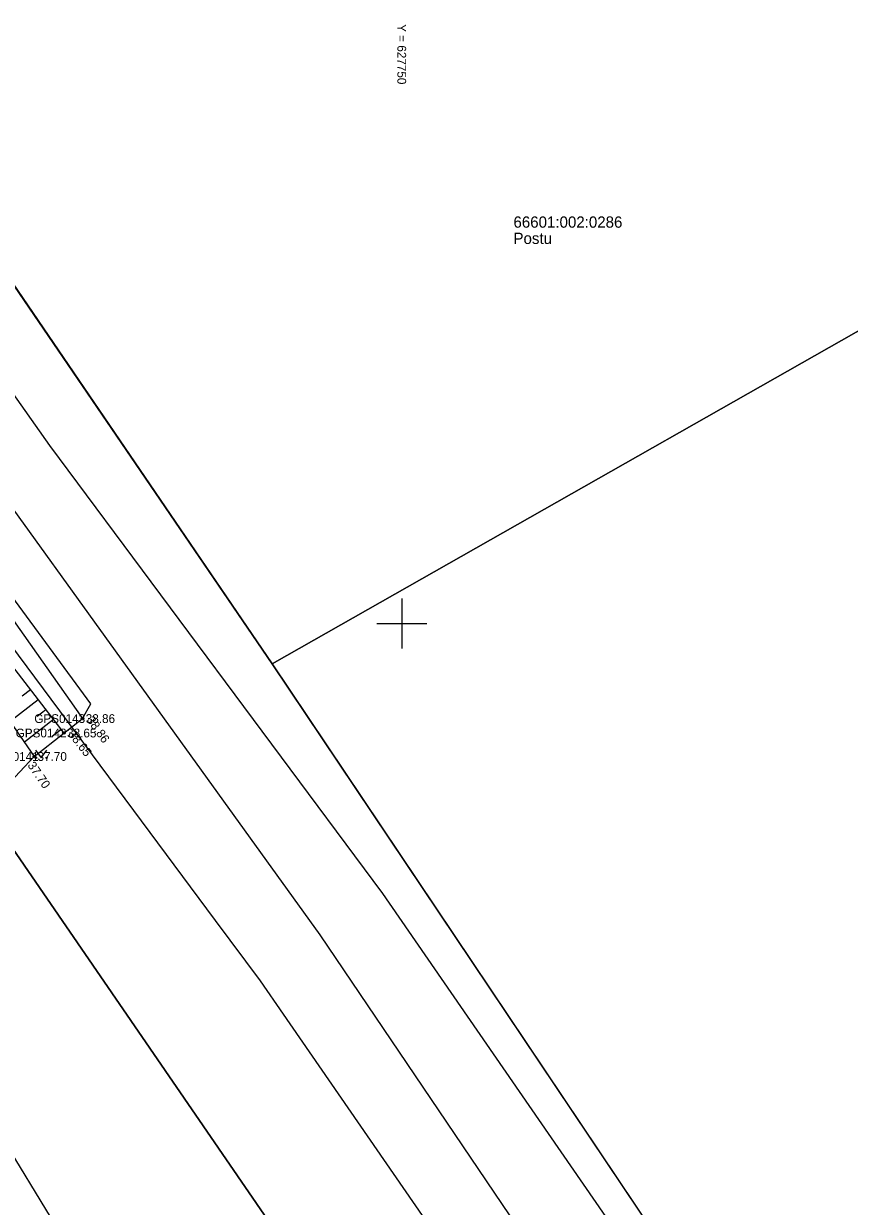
# Model space of a CAD drawing. Extents: x 626224 to 628280, y 6467750 to 6471135.
# Drawn here: x 627719.8 to 627785.8, y 6468553.4 to 6468647.9 of the extents above; entities that cross this region are included whole.
import ezdxf

# ---------------------------------------------------------------- set-up
doc = ezdxf.new("R2010")
doc.units = 0
for name, color, linetype in [('HALJASTUS', 7, 'Continuous'), ('KORGUS-EH2000', 7, 'Continuous'), ('MOOTKORG-EH2000', 7, 'Continuous'), ('MOOTMPUNKT', 7, 'Continuous'), ('MOOTNR', 7, 'Continuous'), ('MOOTPIIR', 7, 'Continuous'), ('MPOHULIIN', 7, 'Continuous'), ('PIIR', 7, 'Continuous'), ('RELJEEF', 7, 'Continuous'), ('TEE', 7, 'Continuous'), ('Tee Liiklusala', 7, 'Continuous'), ('Tee Põhimaantee Püsikate', 7, 'Continuous'), ('VORK', 7, 'Continuous')]:
    doc.layers.add(name, color=color, linetype=linetype)

msp = doc.modelspace()

# ---------------------------------------------------------------- linework, layer by layer
at = {"layer": 'HALJASTUS'}
for p, q in [((627720.731, 6468589.858), (627721.195, 6468589.252)), ((627721.195, 6468589.252), (627721.64, 6468589.858))]:
    msp.add_line(p, q, dxfattribs=at)
for centre in [(627720.794, 6468589.252), (627721.622, 6468589.252)]:
    msp.add_circle(centre, 0.055, dxfattribs=at)
at = {"layer": 'KORGUS-EH2000'}
for centre in [(627724.497, 6468592.392), (627723.007, 6468591.238), (627720.646, 6468589.364)]:
    msp.add_circle(centre, 0.1, dxfattribs=at)
at = {"layer": 'MOOTMPUNKT'}
for centre in [(627724.497, 6468592.392), (627723.007, 6468591.238), (627720.646, 6468589.364)]:
    msp.add_circle(centre, 0.1, dxfattribs=at)
at = {"layer": 'MOOTPIIR'}
msp.add_lwpolyline([(627717.166, 6468585.678), (627720.646, 6468589.364), (627723.007, 6468591.238), (627724.497, 6468592.392), (627725.17, 6468593.561), (627699.891, 6468628.007)], dxfattribs=at)
at = {"layer": 'MPOHULIIN'}
msp.add_lwpolyline([(627776.772, 6468462.547), (627753.896, 6468500.245), (627726.889, 6468544.419), (627704.355, 6468581.436)], dxfattribs=at)
at = {"layer": 'PIIR'}
for points in [[(627433.19, 6469529.94), (627459.99, 6469400.72), (627467.62, 6469361.51), (627515.86, 6469120.25), (627514.14, 6469119.89), (627516.34, 6469107.19), (627530.89, 6469025.52), (627552.51, 6468945.46), (627573.42, 6468886.37), (627594.9, 6468837.52), (627616.28, 6468794.59), (627647.89, 6468735.54), (627664.81, 6468708.59), (627667, 6468705.1), (627666.22, 6468704.47), (627739.66, 6468596.76), (627806.32, 6468497.36)], [(627746.91, 6468541.23), (627688.18, 6468626.77), (627684.35, 6468632.16), (627686.69, 6468632.75), (627663.66, 6468662.2), (627667.34, 6468664.86), (627649.05, 6468692.73), (627646.31, 6468691.19), (627629.12, 6468721.76), (627618.92, 6468715.04), (627606.91, 6468724.16), (627579.16, 6468687.58), (627549.96, 6468707.41), (627588.77, 6468756.22), (627618.05, 6468733.86), (627619.84, 6468735.06), (627604.18, 6468764.29), (627579.83, 6468812.09), (627559.2, 6468856.67), (627547.01, 6468886.57), (627533.67, 6468925.79), (627531.86, 6468935.62), (627512.37, 6469002.4)]]:
    msp.add_lwpolyline(points, dxfattribs=at)
for points in [[(627721.6, 6468730.39), (627736.85, 6468731.37), (627748.32, 6468730.85), (627755.06, 6468730.18), (627763.98, 6468725.35), (627769.77, 6468721.4), (627773.29, 6468719), (627779.7, 6468714.56), (627782.98, 6468713.12), (627824.63, 6468735.56), (627865.5, 6468668.3), (627739.66, 6468596.76), (627666.22, 6468704.47), (627667, 6468705.1), (627667.19, 6468705.25), (627669.44, 6468709.31), (627669.59, 6468709.46), (627678.04, 6468717.3), (627687.85, 6468721.98), (627703.09, 6468726.53)], [(627865.5, 6468668.3), (627932.6, 6468557.07), (627807.45, 6468497.75), (627806.32, 6468497.36), (627739.66, 6468596.76)], [(627746.91, 6468541.23), (627666.94, 6468517.08), (627653, 6468577.43), (627643.52, 6468618.24), (627688.18, 6468626.77)]]:
    msp.add_lwpolyline(points, close=True, dxfattribs=at)
at = {"layer": 'RELJEEF'}
for p, q in [((627720.35, 6468594.682), (627719.69, 6468594.173)), ((627720.961, 6468593.891), (627718.717, 6468592.159)), ((627721.572, 6468593.099), (627720.886, 6468592.57)), ((627722.183, 6468592.307), (627719.855, 6468590.511)), ((627722.794, 6468591.515), (627722.083, 6468590.967))]:
    msp.add_line(p, q, dxfattribs=at)
for points in [[(627664.293, 6468620.969), (627678.559, 6468624.205), (627686.866, 6468625.972), (627692.626, 6468627.53), (627694.391, 6468627.395), (627696.02, 6468626.757), (627697.766, 6468625.488), (627704.517, 6468617.101), (627712.652, 6468604.661), (627723.007, 6468591.238)], [(627664.284, 6468620.85), (627678.877, 6468623.378), (627691.199, 6468626.166), (627693.024, 6468626.089), (627694.96, 6468625.086), (627696.853, 6468623.559), (627702.288, 6468615.532), (627710.843, 6468603.567), (627720.646, 6468589.364)]]:
    msp.add_lwpolyline(points, dxfattribs=at)
at = {"layer": 'TEE'}
msp.add_lwpolyline([(627691.556, 6468636.216), (627691.411, 6468633.572), (627690.377, 6468632.362), (627688.302, 6468631.311), (627683.705, 6468630.285), (627675.534, 6468628.326), (627664.963, 6468626.349), (627655.323, 6468624.553), (627656.855, 6468621.064), (627660.849, 6468621.603), (627663.795, 6468622.181), (627671.677, 6468623.939), (627678.512, 6468625.342), (627686.437, 6468627.071), (627694.212, 6468628.779), (627696.498, 6468628.635), (627697.947, 6468628.287), (627705.762, 6468618.126), (627714.785, 6468606.184), (627724.497, 6468592.392)], dxfattribs=at)
at = {"layer": 'Tee Liiklusala'}
for points in [[(627542.306, 6468967.371), (627548.71, 6468942.84), (627554.3, 6468925.9), (627578.18, 6468861.63), (627588.31, 6468840.05), (627629.52, 6468759.1), (627656.29, 6468714.41), (627663.537, 6468702.423), (627687.78, 6468662.54), (627695.93, 6468652.611), (627708.93, 6468632.54), (627721.86, 6468614.22), (627748.47, 6468578.42), (627760.92, 6468560.36), (627780.56, 6468531.91)], [(627770.48, 6468525.39), (627740.557, 6468568.764), (627738.71, 6468571.44), (627735.13, 6468576.26), (627712.14, 6468607.18), (627694.794, 6468631.457), (627678.044, 6468653.167), (627666.826, 6468668.407), (627651.484, 6468693.118), (627649.736, 6468695.878), (627641.743, 6468708.498), (627640.999, 6468709.875), (627623.478, 6468742.312), (627616.983, 6468754.336), (627595.384, 6468797.487), (627592.828, 6468802.833), (627577.59, 6468834.7), (627567.06, 6468857.03), (627562.51, 6468869.71), (627561.06, 6468873.68), (627543.04, 6468921.76), (627539.249, 6468933.164), (627537.18, 6468939.44), (627530.65, 6468964.53)]]:
    msp.add_lwpolyline(points, dxfattribs=at)
at = {"layer": 'Tee Põhimaantee Püsikate'}
msp.add_lwpolyline([(627700.902, 6468634.138), (627743.449, 6468575.098), (627775.098, 6468528.301), (627799.448, 6468490.206), (627812.119, 6468468.847)], dxfattribs=at)
at = {"layer": 'VORK'}
for p, q in [((627750, 6468602), (627750, 6468598)), ((627748, 6468600), (627752, 6468600))]:
    msp.add_line(p, q, dxfattribs=at)

# ---------------------------------------------------------------- texts
at = {"layer": 'KORGUS-EH2000'}
for s, rotation, p in [(' 38.86', 305.153, (627724.64, 6468592.493)), (' 38.65', 307.65065, (627723.146, 6468591.345)), (' 37.70', 304.61406, (627719.926, 6468588.867))]:
    msp.add_text(s, height=0.7, rotation=rotation, dxfattribs=at).set_placement(p)
at = {"layer": 'MOOTKORG-EH2000'}
for s, p in [(' 38.86', (627724.497, 6468592.042)), (' 38.65', (627723.007, 6468590.888)), (' 37.70', (627720.646, 6468589.014))]:
    msp.add_text(s, height=0.7, dxfattribs=at).set_placement(p)
at = {"layer": 'MOOTNR'}
for s, p in [('GPS0143 ', (627720.647, 6468592.042)), ('GPS0142 ', (627719.158, 6468590.888)), ('GPS0141 ', (627716.937, 6468589.014))]:
    msp.add_text(s, height=0.7, dxfattribs=at).set_placement(p)
at = {"layer": 'PIIR'}
for s, p in [('66601:002:0286', (627758.925, 6468631.63)), ('Postu', (627758.925, 6468630.33))]:
    msp.add_text(s, height=0.9, dxfattribs=at).set_placement(p)
at = {"layer": 'VORK'}
msp.add_text('Y = 627750 ', height=0.7, rotation=270, dxfattribs=at).set_placement((627749.65, 6468647.9))

doc.saveas('drawing.dxf')
